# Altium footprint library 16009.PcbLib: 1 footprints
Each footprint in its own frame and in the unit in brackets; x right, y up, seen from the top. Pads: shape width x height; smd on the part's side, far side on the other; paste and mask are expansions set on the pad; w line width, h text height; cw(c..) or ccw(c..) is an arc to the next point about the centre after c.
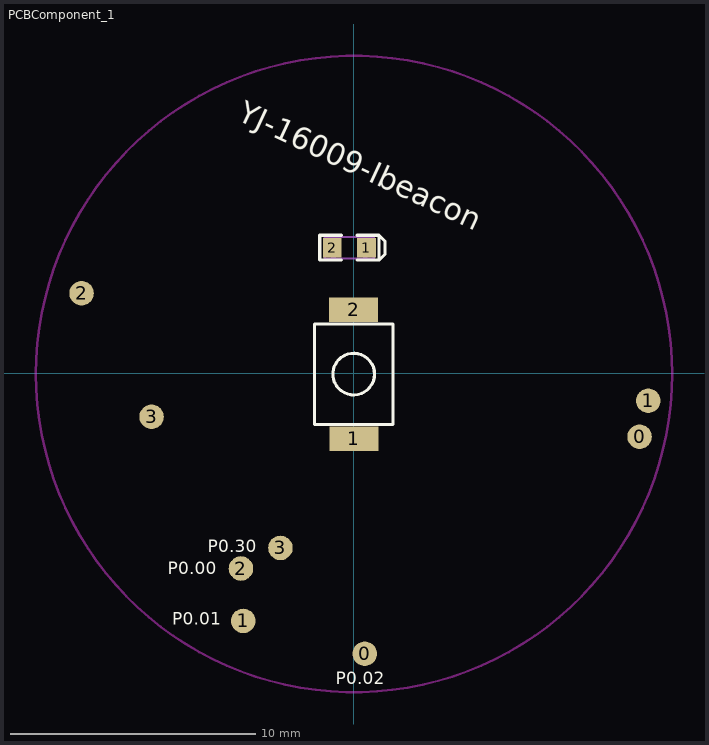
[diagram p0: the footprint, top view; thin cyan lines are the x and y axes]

## PCBComponent_1 [mm]
pads (12):
  round 1 smd: 0(0.451,-11.444) 0(11.666,-2.584) 1(-4.509,-10.104) 1(12.025,-1.123) 2(-11.106,3.27) 2(-4.599,-7.964) 3(-8.249,-1.774) 3(-2.989,-7.124)
  rect 2x1 smd: 1(0.006,-2.661) 2(-0.004,2.599)
  rect 0.762x0.813 smd: 1(0.52,5.126) 2(-0.877,5.126)
Top Overlay:
  circle w0.127: c0.001,-0.03 r0.85
  lines w0.127: -0.496,4.618 -1.385,4.618 -1.385,5.634 -0.496,5.634 ; 0.139,4.618 1.028,4.618 ; 0.139,5.634 1.028,5.634 ; 1.028,4.618 1.282,4.872 1.282,5.38 1.028,5.634 ; 1.028,4.618 1.028,5.634 ; -1.599,-2.08 1.601,-2.08 1.601,2.02 -1.599,2.02 -1.599,-2.08
  text "P0.30" at -5.949,-7.294 h0.5
  text "P0.00" at -7.579,-8.204 h0.5
  text "P0.01" at -7.409,-10.264 h0.5
  text "P0.02" at -0.739,-12.684 h0.5
  text "YJ-16009-Ibeacon" at -4.799,10.356 h0.9
Keep-Out Layer:
  circle w0.1: c0.013,-0.027 r12.985
Mechanical 7:
  lines w0.1: -0.879,4.687 -0.879,5.565 ; -0.779,4.687 -0.779,5.565 ; 0.421,4.687 0.421,5.565 ; 0.521,4.687 0.521,5.565 ; -1.179,4.687 0.821,4.687 0.821,5.565 -1.179,5.565 -1.179,4.687
  text "LED_G" at 0.321,5.251 h0.3
3D body: height 1.8, standoff 0, extent -1.599,-2.086 1.601,2.029
3D body: height 0.1, standoff 0, extent -0.837,2.003 0.839,2.943
3D body: height 0.1, standoff 0, extent -0.837,-3.038 0.839,-2.099
3D body: height 2.3, standoff 1.8, extent -0.997,-1.021 0.999,0.971
3D body: height 0.6, standoff 0, extent -0.996,4.726 0.625,5.526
